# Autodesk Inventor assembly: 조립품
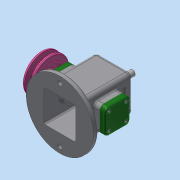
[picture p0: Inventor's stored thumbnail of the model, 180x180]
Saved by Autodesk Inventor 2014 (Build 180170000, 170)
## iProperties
Created: 2021-08
Part Number: 조립품
Document SubType Name: Assembly
Designer: dg
Author: dg
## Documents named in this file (16)
- C:\Users\dg\Desktop\710806V1012\조립품.iam
- C:\Users\dg\Desktop\710806V1012\본체.ipt
- C:\Users\dg\Desktop\710806V1012\편심축.ipt
- C:\Users\dg\Desktop\710806V1012\베어링 12x32x10.ipt
- C:\Users\dg\Desktop\710806V1012\키 4x4x10.ipt
- C:\Users\dg\Desktop\710806V1012\V벨트풀리.ipt
- C:\Users\dg\Desktop\710806V1012\멈춤나사 M3x8.ipt
- C:\Users\dg\Desktop\710806V1012\링크.ipt
- C:\Users\dg\Desktop\710806V1012\부시.ipt
- C:\Users\dg\Desktop\710806V1012\슬라이드.ipt
- C:\Users\dg\Desktop\710806V1012\뒤커버.ipt
- C:\Users\dg\Desktop\710806V1012\핀 5x18.ipt
- C:\Users\dg\Desktop\710806V1012\고정핀 1.2x8.ipt
- C:\Users\dg\Desktop\710806V1012\앞커버.ipt
- C:\Users\dg\Desktop\710806V1012\볼트 M4.ipt
- C:\Users\dg\Desktop\710806V1012\오일 실 12 25 7.ipt
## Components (3 placed, 3 different names)
1. V벨트풀리:1
2. 핀 5x18:1
3. 고정핀 1.2x8:1
## Component patterns: 구성요소 패턴 1:2 (2 elements)
